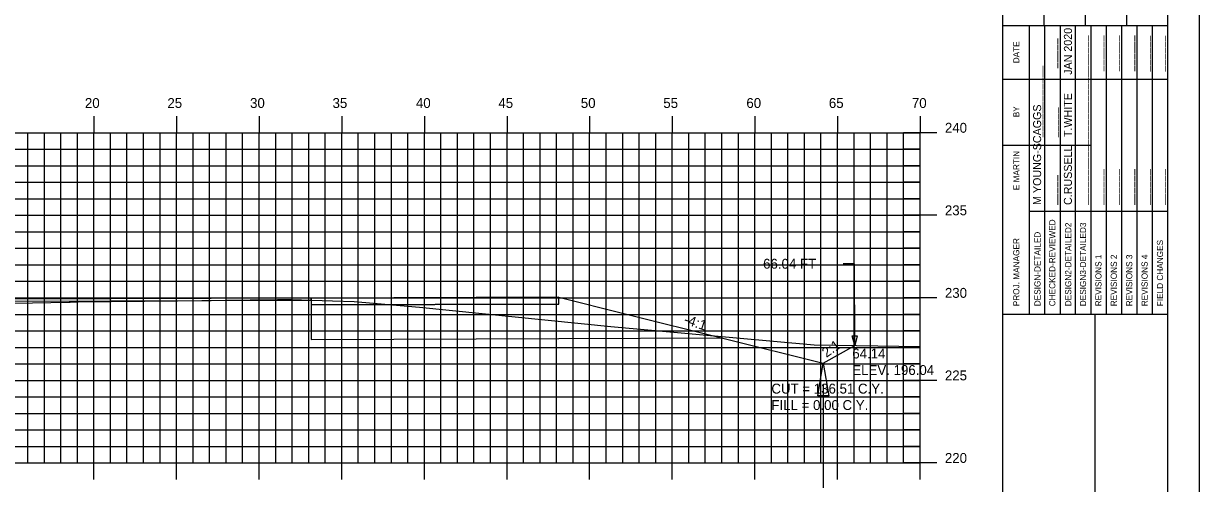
# Model space of a CAD drawing. Extents: x 1137211 to 1137381, y 608981 to 609091.
# Drawn here: x 1137309.6 to 1137380.8, y 609019.1 to 609047 of the extents above; entities that cross this region are included whole.
import ezdxf

# ---------------------------------------------------------------- set-up
doc = ezdxf.new("R2010")
doc.units = 0
for name, color, linetype in [('ANNOTATION', 7, 'Continuous'), ('BORDER', 7, 'Continuous'), ('D_Drainage_Ditch_Line', 7, 'Continuous'), ('D_Roadway_Edge_Shoulder', 7, 'Continuous'), ('D_Roadway_SubGrade', 7, 'Continuous'), ('D_Text_Standard', 7, 'Continuous'), ('H_V ANNOTATION', 7, 'Continuous'), ('MAJOR', 7, 'Continuous'), ('MINOR', 7, 'Continuous'), ('PLOT BOUNDARY', 7, 'Continuous'), ('S_Roadway_Centerline', 7, 'Continuous')]:
    doc.layers.add(name, color=color, linetype=linetype)

msp = doc.modelspace()

# ---------------------------------------------------------------- linework, layer by layer
at = {"layer": 'BORDER'}
for p, q in [((1137368.897, 608984.335), (1137368.897, 609089.335)), ((1137371.397, 609046.838), (1137371.397, 609055.485)), ((1137373.897, 609046.838), (1137373.897, 609055.485)), ((1137376.397, 609046.838), (1137376.397, 609055.485)), ((1137368.897, 609046.838), (1137378.897, 609046.838)), ((1137368.897, 609029.338), (1137378.897, 609029.338)), ((1137374.488, 608994.338), (1137374.488, 609029.338))]:
    msp.add_line(p, q, dxfattribs=at)
msp.add_lwpolyline([(1137218.897, 608984.335), (1137378.897, 608984.335), (1137378.897, 609089.335), (1137218.897, 609089.335)], close=True, dxfattribs=at)
for points in [[(1137370.511, 609043.588), (1137370.511, 609046.838)], [(1137371.444, 609029.341), (1137371.444, 609046.838)], [(1137372.376, 609046.838), (1137372.376, 609029.341)], [(1137373.307, 609029.341), (1137373.307, 609046.838)], [(1137374.239, 609029.341), (1137374.239, 609046.838)], [(1137375.171, 609029.341), (1137375.171, 609046.838)], [(1137376.102, 609029.341), (1137376.102, 609046.838)], [(1137377.034, 609029.341), (1137377.034, 609046.838)], [(1137377.966, 609029.341), (1137377.966, 609046.838)], [(1137370.512, 609029.341), (1137370.512, 609046.132)], [(1137368.897, 609043.588), (1137378.897, 609043.588)], [(1137368.897, 609039.588), (1137370.512, 609039.588)], [(1137370.511, 609039.588), (1137374.238, 609039.588)], [(1137370.511, 609035.588), (1137378.897, 609035.588)]]:
    msp.add_lwpolyline(points, dxfattribs=at)
at = {"layer": 'D_Drainage_Ditch_Line'}
msp.add_line((1137358.036, 609025.06), (1137358.036, 609018.817), dxfattribs=at)
msp.add_lwpolyline([(1137358.364, 609024.404), (1137357.708, 609024.404), (1137358.036, 609026.372)], close=True, dxfattribs=at)
at = {"layer": 'D_Roadway_Edge_Shoulder'}
for points in [[(1137327.036, 609030.192), (1137327.036, 609030.317), (1137308.896, 609030.25), (1137308.896, 609030.125)], [(1137327.036, 609030.317), (1137327.036, 609029.901), (1137342.036, 609029.956), (1137342.036, 609030.372)]]:
    msp.add_lwpolyline(points, close=True, dxfattribs=at)
at = {"layer": 'D_Roadway_SubGrade'}
for p, q in [((1137342.036, 609027.872), (1137351.891, 609027.909)), ((1137358.036, 609026.372), (1137359.936, 609027.452))]:
    msp.add_line(p, q, dxfattribs=at)
for points in [[(1137342.036, 609029.956), (1137327.036, 609029.901), (1137327.036, 609027.817), (1137342.036, 609027.872)], [(1137342.036, 609030.372), (1137346.036, 609029.372), (1137358.036, 609026.372)]]:
    msp.add_lwpolyline(points, dxfattribs=at)
at = {"layer": 'D_Text_Standard'}
msp.add_lwpolyline([(1137359.936, 609027.452), (1137359.919, 609032.399), (1137359.239, 609032.399)], dxfattribs=at)
msp.add_lwpolyline([(1137359.936, 609027.452), (1137359.789, 609028.034), (1137360.08, 609028.035)], close=True, dxfattribs=at)
at = {"layer": 'MAJOR'}
for p, q in [((1137313.896, 609041.337), (1137313.896, 609040.335)), ((1137318.896, 609041.337), (1137318.896, 609040.335)), ((1137323.896, 609041.337), (1137323.896, 609040.335)), ((1137328.896, 609041.337), (1137328.896, 609040.335)), ((1137333.896, 609041.337), (1137333.896, 609040.335)), ((1137338.896, 609041.337), (1137338.896, 609040.335)), ((1137343.896, 609041.337), (1137343.896, 609040.335)), ((1137348.896, 609041.337), (1137348.896, 609040.335)), ((1137353.896, 609041.337), (1137353.896, 609040.335)), ((1137358.896, 609041.337), (1137358.896, 609040.335)), ((1137363.896, 609041.337), (1137363.896, 609040.335)), ((1137223.896, 609040.335), (1137363.896, 609040.335)), ((1137223.896, 609040.335), (1137363.896, 609040.335)), ((1137313.896, 609020.335), (1137313.896, 609040.335)), ((1137318.896, 609020.335), (1137318.896, 609040.335)), ((1137323.896, 609020.335), (1137323.896, 609040.335)), ((1137328.896, 609020.335), (1137328.896, 609040.335)), ((1137333.896, 609020.335), (1137333.896, 609040.335)), ((1137338.896, 609020.335), (1137338.896, 609040.335)), ((1137343.896, 609020.335), (1137343.896, 609040.335)), ((1137348.896, 609020.335), (1137348.896, 609040.335)), ((1137353.896, 609020.335), (1137353.896, 609040.335)), ((1137358.896, 609020.335), (1137358.896, 609040.335)), ((1137364.898, 609040.335), (1137362.894, 609040.335)), ((1137363.896, 609020.335), (1137363.896, 609040.335)), ((1137363.896, 609020.335), (1137363.896, 609040.335)), ((1137223.896, 609035.335), (1137363.896, 609035.335)), ((1137364.898, 609035.335), (1137362.894, 609035.335)), ((1137223.896, 609030.335), (1137363.896, 609030.335)), ((1137364.898, 609030.335), (1137362.894, 609030.335)), ((1137223.896, 609025.335), (1137363.896, 609025.335)), ((1137364.898, 609025.335), (1137362.894, 609025.335)), ((1137223.896, 609020.335), (1137363.896, 609020.335)), ((1137223.896, 609020.335), (1137363.896, 609020.335)), ((1137313.896, 609019.333), (1137313.896, 609020.335)), ((1137318.896, 609019.333), (1137318.896, 609020.335)), ((1137323.896, 609019.333), (1137323.896, 609020.335)), ((1137328.896, 609019.333), (1137328.896, 609020.335)), ((1137333.896, 609019.333), (1137333.896, 609020.335)), ((1137338.896, 609019.333), (1137338.896, 609020.335)), ((1137343.896, 609019.333), (1137343.896, 609020.335)), ((1137348.896, 609019.333), (1137348.896, 609020.335)), ((1137353.896, 609019.333), (1137353.896, 609020.335)), ((1137358.896, 609019.333), (1137358.896, 609020.335)), ((1137364.898, 609020.335), (1137362.894, 609020.335)), ((1137363.896, 609019.333), (1137363.896, 609020.335))]:
    msp.add_line(p, q, dxfattribs=at)
at = {"layer": 'MINOR'}
for p, q in [((1137309.896, 609020.335), (1137309.896, 609040.335)), ((1137310.896, 609020.335), (1137310.896, 609040.335)), ((1137311.896, 609020.335), (1137311.896, 609040.335)), ((1137312.896, 609020.335), (1137312.896, 609040.335)), ((1137314.896, 609020.335), (1137314.896, 609040.335)), ((1137315.896, 609020.335), (1137315.896, 609040.335)), ((1137316.896, 609020.335), (1137316.896, 609040.335)), ((1137317.896, 609020.335), (1137317.896, 609040.335)), ((1137319.896, 609020.335), (1137319.896, 609040.335)), ((1137320.896, 609020.335), (1137320.896, 609040.335)), ((1137321.896, 609020.335), (1137321.896, 609040.335)), ((1137322.896, 609020.335), (1137322.896, 609040.335)), ((1137324.896, 609020.335), (1137324.896, 609040.335)), ((1137325.896, 609020.335), (1137325.896, 609040.335)), ((1137326.896, 609020.335), (1137326.896, 609040.335)), ((1137327.896, 609020.335), (1137327.896, 609040.335)), ((1137329.896, 609020.335), (1137329.896, 609040.335)), ((1137330.896, 609020.335), (1137330.896, 609040.335)), ((1137331.896, 609020.335), (1137331.896, 609040.335)), ((1137332.896, 609020.335), (1137332.896, 609040.335)), ((1137334.896, 609020.335), (1137334.896, 609040.335)), ((1137335.896, 609020.335), (1137335.896, 609040.335)), ((1137336.896, 609020.335), (1137336.896, 609040.335)), ((1137337.896, 609020.335), (1137337.896, 609040.335)), ((1137339.896, 609020.335), (1137339.896, 609040.335)), ((1137340.896, 609020.335), (1137340.896, 609040.335)), ((1137341.896, 609020.335), (1137341.896, 609040.335)), ((1137342.896, 609020.335), (1137342.896, 609040.335)), ((1137344.896, 609020.335), (1137344.896, 609040.335)), ((1137345.896, 609020.335), (1137345.896, 609040.335)), ((1137346.896, 609020.335), (1137346.896, 609040.335)), ((1137347.896, 609020.335), (1137347.896, 609040.335)), ((1137349.896, 609020.335), (1137349.896, 609040.335)), ((1137350.896, 609020.335), (1137350.896, 609040.335)), ((1137351.896, 609020.335), (1137351.896, 609040.335)), ((1137352.896, 609020.335), (1137352.896, 609040.335)), ((1137354.896, 609020.335), (1137354.896, 609040.335)), ((1137355.896, 609020.335), (1137355.896, 609040.335)), ((1137356.896, 609020.335), (1137356.896, 609040.335)), ((1137357.896, 609020.335), (1137357.896, 609040.335)), ((1137359.896, 609020.335), (1137359.896, 609040.335)), ((1137360.896, 609020.335), (1137360.896, 609040.335)), ((1137361.896, 609020.335), (1137361.896, 609040.335)), ((1137362.896, 609020.335), (1137362.896, 609040.335)), ((1137223.896, 609039.335), (1137363.896, 609039.335)), ((1137363.896, 609039.335), (1137362.894, 609039.335)), ((1137223.896, 609038.335), (1137363.896, 609038.335)), ((1137363.896, 609038.335), (1137362.894, 609038.335)), ((1137223.896, 609037.335), (1137363.896, 609037.335)), ((1137363.896, 609037.335), (1137362.894, 609037.335)), ((1137223.896, 609036.335), (1137363.896, 609036.335)), ((1137363.896, 609036.335), (1137362.894, 609036.335)), ((1137223.896, 609034.335), (1137363.896, 609034.335)), ((1137363.896, 609034.335), (1137362.894, 609034.335)), ((1137223.896, 609033.335), (1137363.896, 609033.335)), ((1137363.896, 609033.335), (1137362.894, 609033.335)), ((1137223.896, 609032.335), (1137363.896, 609032.335)), ((1137363.896, 609032.335), (1137362.894, 609032.335)), ((1137223.896, 609031.335), (1137363.896, 609031.335)), ((1137363.896, 609031.335), (1137362.894, 609031.335)), ((1137223.896, 609029.335), (1137363.896, 609029.335)), ((1137363.896, 609029.335), (1137362.894, 609029.335)), ((1137223.896, 609028.335), (1137363.896, 609028.335)), ((1137363.896, 609028.335), (1137362.894, 609028.335)), ((1137223.896, 609027.335), (1137363.896, 609027.335)), ((1137363.896, 609027.335), (1137362.894, 609027.335)), ((1137223.896, 609026.335), (1137363.896, 609026.335)), ((1137363.896, 609026.335), (1137362.894, 609026.335)), ((1137223.896, 609024.335), (1137363.896, 609024.335)), ((1137363.896, 609024.335), (1137362.894, 609024.335)), ((1137223.896, 609023.335), (1137363.896, 609023.335)), ((1137363.896, 609023.335), (1137362.894, 609023.335)), ((1137223.896, 609022.335), (1137363.896, 609022.335)), ((1137363.896, 609022.335), (1137362.894, 609022.335)), ((1137223.896, 609021.335), (1137363.896, 609021.335)), ((1137363.896, 609021.335), (1137362.894, 609021.335))]:
    msp.add_line(p, q, dxfattribs=at)
at = {"layer": 'PLOT BOUNDARY'}
msp.add_lwpolyline([(1137210.803, 608981.276), (1137380.803, 608981.276), (1137380.803, 609091.276), (1137210.803, 609091.276)], close=True, dxfattribs=at)
at = {"layer": 'S_Roadway_Centerline'}
msp.add_lwpolyline([(1137304.633, 609029.928), (1137312.395, 609030.077), (1137312.395, 609030.077), (1137312.449, 609030.078), (1137312.934, 609030.083), (1137318.952, 609030.154), (1137323.342, 609030.205), (1137325.008, 609030.227), (1137325.322, 609030.231), (1137325.823, 609030.237), (1137328.34, 609030.144), (1137329.65, 609030.113), (1137333.598, 609029.768), (1137345.176, 609028.593), (1137357.493, 609027.498), (1137363.896, 609027.379)], dxfattribs=at)

# ---------------------------------------------------------------- texts
at = {"layer": 'ANNOTATION'}
for s, rotation, p in [('-4:1', 341.48743, (1137349.551, 609028.788)), ('2:1', 35.40676, (1137358.223, 609026.691))]:
    msp.add_text(s, height=0.6, rotation=rotation, dxfattribs=at).set_placement(p)
at = {"layer": 'BORDER'}
for s, height, p in [('JAN 2020', 0.4845, (1137373.083, 609043.843)), ('DATE', 0.3714, (1137369.901, 609044.544)), ('_____', 0.4845, (1137372.114, 609044.243)), ('______', 0.4845, (1137373.977, 609044.063)), ('______', 0.4845, (1137374.909, 609044.065)), ('______', 0.4845, (1137375.841, 609044.067)), ('______', 0.4845, (1137376.772, 609044.067)), ('______', 0.4845, (1137377.704, 609044.036)), ('______', 0.4845, (1137378.636, 609044.036)), ('____________', 0.48455, (1137371.219, 609040.073)), ('____________', 0.48455, (1137373.977, 609040.073)), ('T.WHITE', 0.4845, (1137373.083, 609040.073)), ('M YOUNG-SCAGGS', 0.48455, (1137371.219, 609035.961)), ('BY', 0.3714, (1137369.901, 609041.273)), ('_____', 0.4845, (1137372.151, 609040.073)), ('____________', 0.48455, (1137373.977, 609035.961)), ('E MARTIN', 0.3727, (1137369.901, 609036.855)), ('C.RUSSELL', 0.4845, (1137373.083, 609035.961)), ('_____', 0.4845, (1137372.114, 609035.961)), ('______', 0.4845, (1137374.909, 609035.961)), ('______', 0.4845, (1137375.841, 609035.961)), ('______', 0.4845, (1137376.772, 609035.961)), ('______', 0.4845, (1137377.704, 609035.961)), ('______', 0.4845, (1137378.636, 609035.961)), ('CHECKED-REVIEWED', 0.37275, (1137372.078, 609029.826)), ('DESIGN3-DETAILED3', 0.37275, (1137373.941, 609029.826)), ('DESIGN-DETAILED', 0.37275, (1137371.183, 609029.826)), ('DESIGN2-DETAILED2', 0.37275, (1137373.046, 609029.826)), ('PROJ. MANAGER', 0.37275, (1137369.901, 609029.826)), ('FIELD CHANGES', 0.37275, (1137378.599, 609029.826)), ('REVISIONS 1', 0.37275, (1137374.873, 609029.826)), ('REVISIONS 2', 0.37275, (1137375.804, 609029.826)), ('REVISIONS 3', 0.37275, (1137376.736, 609029.826)), ('REVISIONS 4', 0.37275, (1137377.668, 609029.826))]:
    msp.add_text(s, height=height, rotation=90, dxfattribs=at).set_placement(p)
at = {"layer": 'D_Text_Standard'}
for s, p in [('66.04 FT', (1137354.395, 609032.099)), ('64.14', (1137359.793, 609026.663)), ('ELEV. 196.04', (1137359.793, 609025.661)), ('CUT = 136.51 C.Y.', (1137354.896, 609024.535)), ('FILL = 0.00 C.Y.', (1137354.896, 609023.539))]:
    msp.add_text(s, height=0.6, dxfattribs=at).set_placement(p)
at = {"layer": 'H_V ANNOTATION'}
for s, p in [('20', (1137313.35, 609041.835)), ('25', (1137318.342, 609041.835)), ('30', (1137323.345, 609041.835)), ('35', (1137328.337, 609041.835)), ('40', (1137333.382, 609041.835)), ('45', (1137338.374, 609041.835)), ('50', (1137343.361, 609041.835)), ('55', (1137348.353, 609041.835)), ('60', (1137353.382, 609041.835)), ('65', (1137358.374, 609041.835)), ('70', (1137363.398, 609041.835)), ('240', (1137365.396, 609040.335)), ('235', (1137365.396, 609035.335)), ('230', (1137365.396, 609030.335)), ('225', (1137365.396, 609025.335)), ('220', (1137365.396, 609020.335))]:
    msp.add_text(s, height=0.6, dxfattribs=at).set_placement(p)

doc.saveas('drawing.dxf')
